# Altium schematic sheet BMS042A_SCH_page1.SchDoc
size 431 x 279 mm; Date: Not shown in title block; ApprovedBy: Not shown in title block; CheckedBy: Not shown in title block; Author: Not shown in title block; CompanyName: Not shown in title block; DrawnBy: Pengzhao Zhu; Engineer: Not shown in title block; Organization: Not shown in title block; Address1: Not shown in title block; Address2: Not shown in title block; Address3: Not shown in title block; Address4: Not shown in title block; DocumentNumber: 1; Revision: Use project parameter SCH_Rev; SheetNumber: 1; SheetTotal: 4; PageSetup: Record=PageOptions¦CenterHorizontal=True¦CenterVertical=True¦PrintScale=1.00¦XCorrection=1.00¦YCorrection=1.00¦PrintKind=0¦BorderSize=5000000¦LeftOffset=0¦BottomOffset=0¦Orientation=2¦PaperLength=1000¦PaperWidth=1000¦Scale=100¦PaperSource=15¦PrintQuality=600¦MediaType=1¦DitherType=10¦PaperKind=Letter¦PrintScaleMode=1
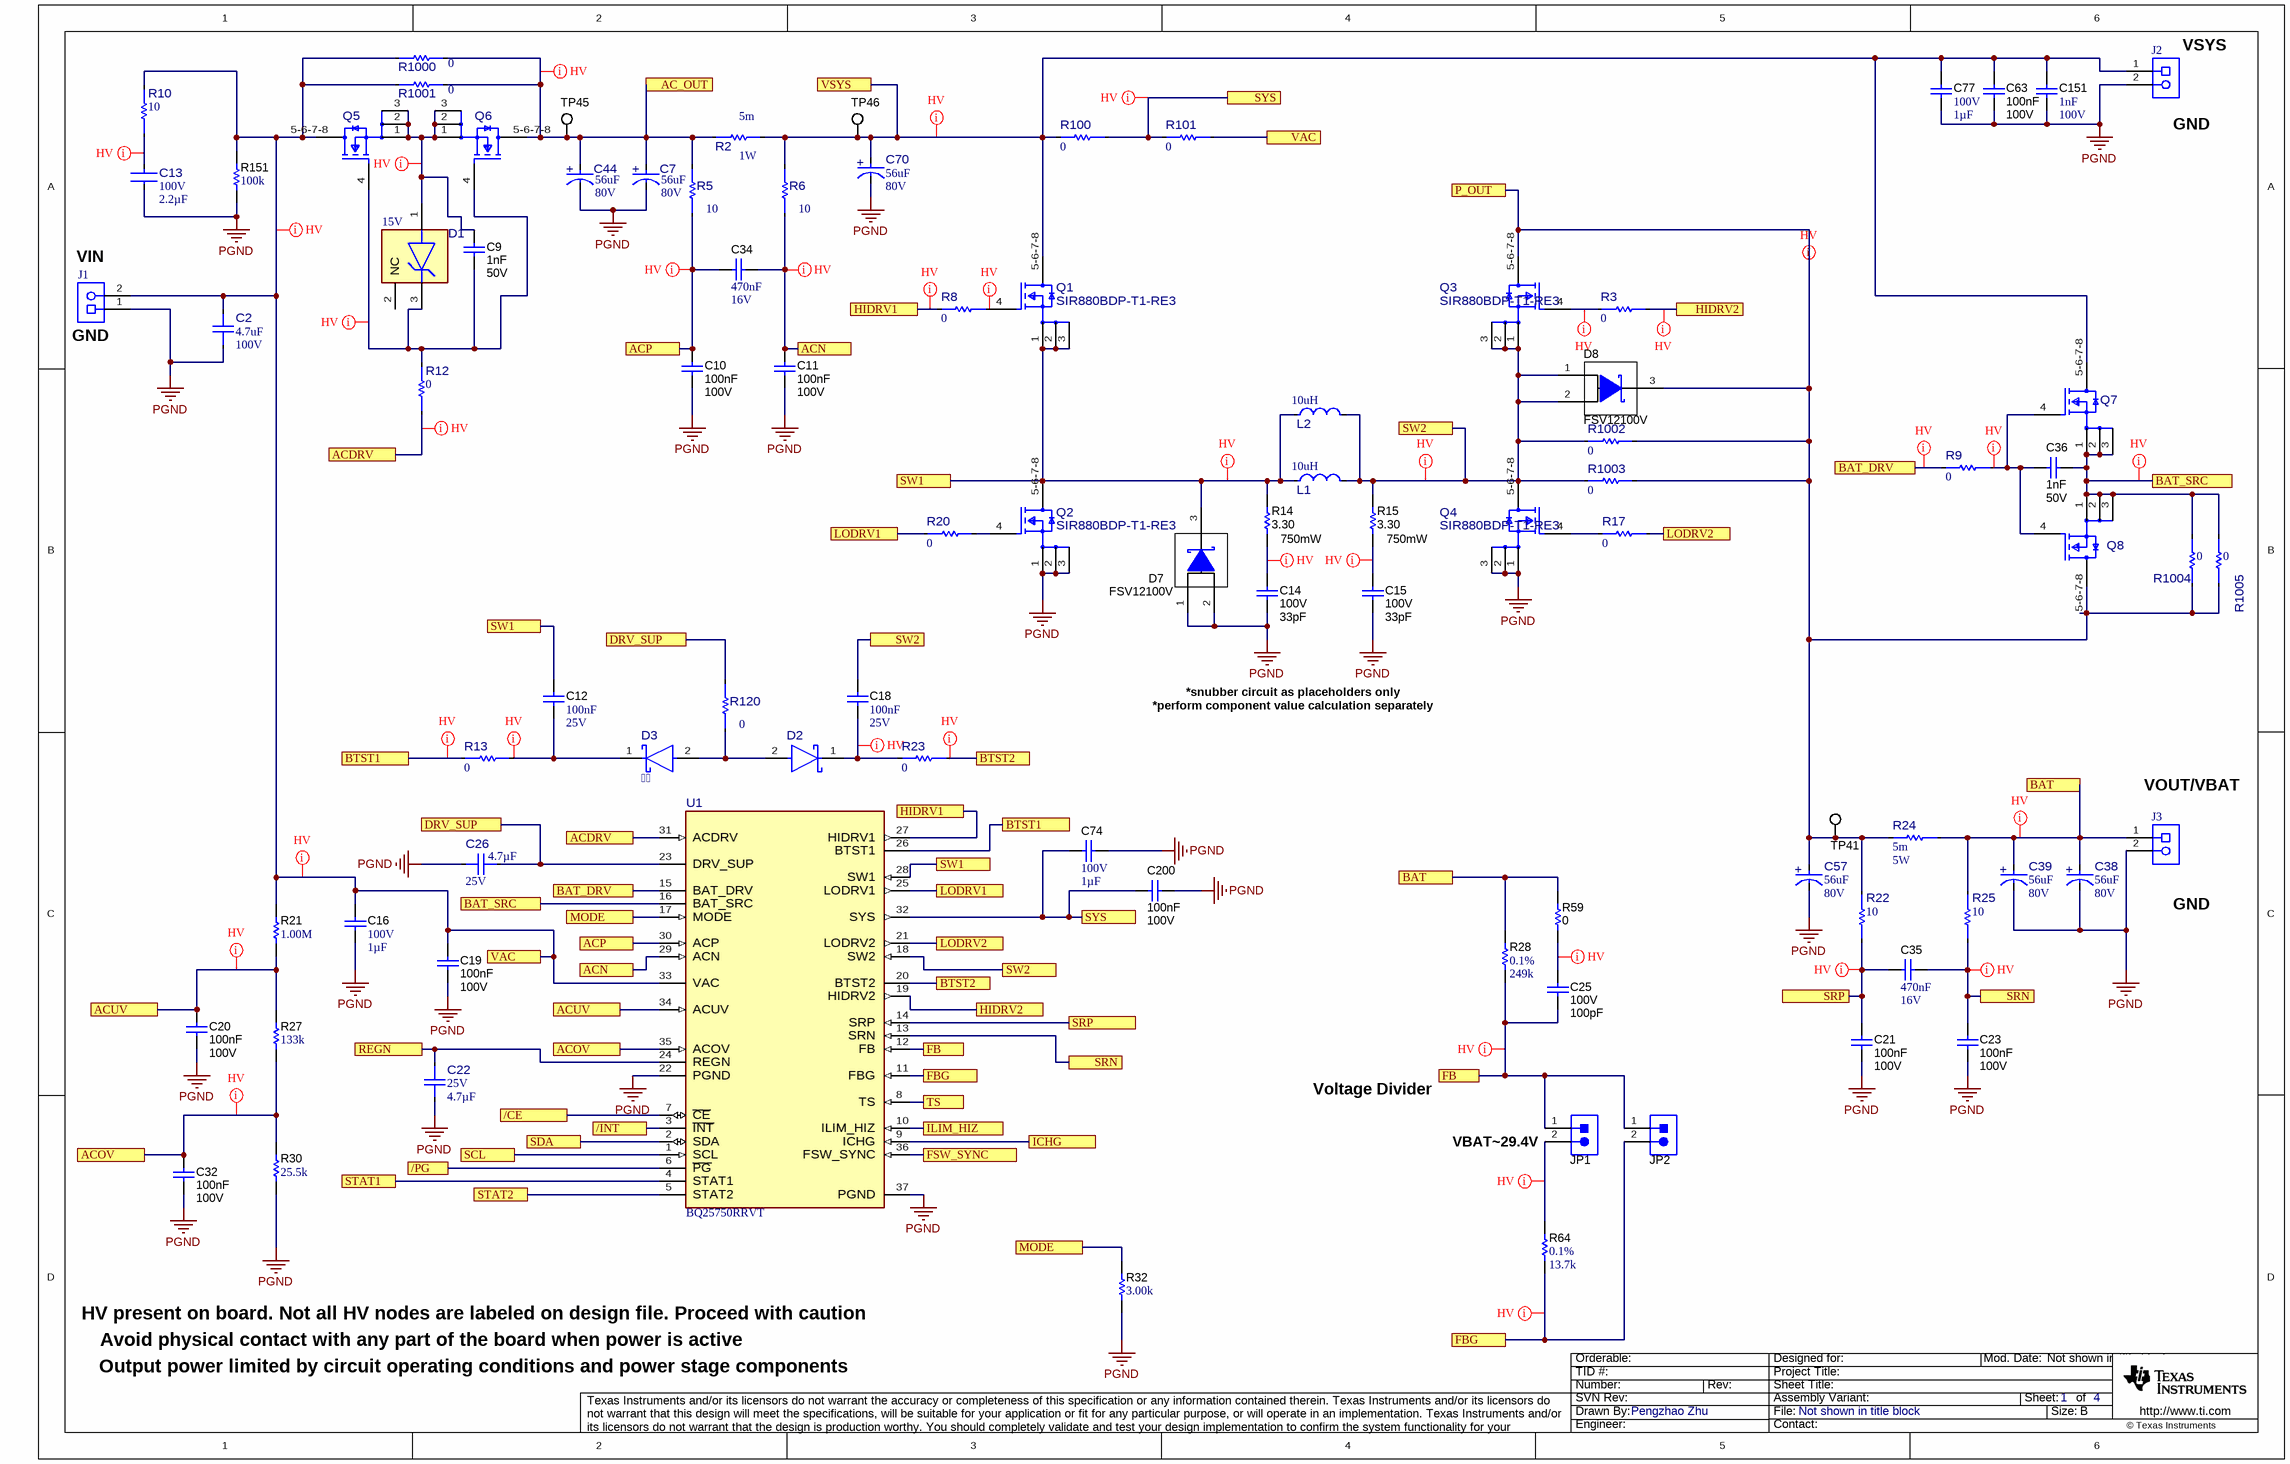
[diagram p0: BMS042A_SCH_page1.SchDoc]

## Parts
C2  ValueDisplayed: 4.7uF  VDC_V: 100V  [FP-GCJ32DC72A475KE01L_1210-MFG]  (hidden comment: GCJ32DC72A475KE01L)
C7  ValueDisplayed: 56uF  VDC_V: 80V  [FP-80SXV56M_SMT_CAP_10MM3_10MM3-MFG]  (hidden comment: 80SXV56M)
C9  Cap_F: 1nF  VDC_V: 50V  [0603_HV]  (hidden comment: C0603C102J5RACTU)
C10  Cap_F: 100nF  VDC_V: 100V  [0603_HV]  (hidden comment: HMK107B7104KAHT)
C11  Cap_F: 100nF  VDC_V: 100V  [0603_HV]  (hidden comment: HMK107B7104KAHT)
C12  Cap_F: 100nF  VDC_V: 25V  [0603_HV]  (hidden comment: 06033C104KAT2A)
C13  VDC_V: 100V  Cap_F: 2.2µF  [FP-CGA6N3X7R2A225K230AE_1210-MFG]  (hidden comment: CGA6N3X7R2A225K230AE)
C14  VDC_V: 100V  ValueDisplayed: 33pF  [0603_HV]  (hidden comment: 06031A330JAT2A)
C15  VDC_V: 100V  ValueDisplayed: 33pF  [0603_HV]  (hidden comment: 06031A330JAT2A)
C16  VDC_V: 100V  Cap_F: 1µF  [0805_150]  (hidden comment: 08051C105K4Z2A)
C18  Cap_F: 100nF  VDC_V: 25V  [0603_HV]  (hidden comment: 06033C104KAT2A)
C19  Cap_F: 100nF  VDC_V: 100V  [0603_HV]  (hidden comment: HMK107B7104KAHT)
C20  Cap_F: 100nF  VDC_V: 100V  [0603_HV]  (hidden comment: HMK107B7104KAHT)
C21  Cap_F: 100nF  VDC_V: 100V  [0603_HV]  (hidden comment: HMK107B7104KAHT)
C22  VDC_V: 25V  Cap_F: 4.7µF  [FP-CGA4J1X7R1E475K125AE_0805-MFG]  (hidden comment: CGA4J1X7R1E475K125AE)
C23  Cap_F: 100nF  VDC_V: 100V  [0603_HV]  (hidden comment: HMK107B7104KAHT)
C25  VDC_V: 100V  ValueDisplayed: 100pF  [0603_HV]  (hidden comment: GCM1885C2A101JA16D)
C26  VDC_V: 25V  Cap_F: 4.7µF  [FP-CGA4J1X7R1E475K125AE_0805-MFG]  (hidden comment: CGA4J1X7R1E475K125AE)
C32  Cap_F: 100nF  VDC_V: 100V  [0603_HV]  (hidden comment: HMK107B7104KAHT)
C34  Cap_F: 470nF  VDC_V: 16V  [0603]  (hidden comment: C0603C474K4RACTU)
C35  Cap_F: 470nF  VDC_V: 16V  [0603]  (hidden comment: C0603C474K4RACTU)
C36  Cap_F: 1nF  VDC_V: 50V  [0603_HV]  (hidden comment: C0603C102J5RACTU)
C38  ValueDisplayed: 56uF  VDC_V: 80V  [FP-80SXV56M_SMT_CAP_10MM3_10MM3-MFG]  (hidden comment: 80SXV56M)
C39  ValueDisplayed: 56uF  VDC_V: 80V  [FP-80SXV56M_SMT_CAP_10MM3_10MM3-MFG]  (hidden comment: 80SXV56M)
C44  ValueDisplayed: 56uF  VDC_V: 80V  [FP-80SXV56M_SMT_CAP_10MM3_10MM3-MFG]  (hidden comment: 80SXV56M)
C57  ValueDisplayed: 56uF  VDC_V: 80V  [FP-80SXV56M_SMT_CAP_10MM3_10MM3-MFG]  (hidden comment: 80SXV56M)
C63  Cap_F: 100nF  VDC_V: 100V  [0603L]  (hidden comment: HMK107B7104KAHT)
C70  ValueDisplayed: 56uF  VDC_V: 80V  [FP-80SXV56M_SMT_CAP_10MM3_10MM3-MFG]  (hidden comment: 80SXV56M)
C74  VDC_V: 100V  Cap_F: 1µF  [0805_150]  (hidden comment: 08051C105K4Z2A)
C77  VDC_V: 100V  Cap_F: 1µF  [0805_150]  (hidden comment: 08051C105K4Z2A)
C151  Cap_F: 1nF  VDC_V: 100V  [0603]  (hidden comment: CGA3E2X7R2A102K080AA)
C200  Cap_F: 100nF  VDC_V: 100V  [0603_HV]  (hidden comment: HMK107B7104KAHT)
D1  Vz_V: 15V  [FP-SZBZX84C15LT3G_SOT23-MFG]
D2  (no value)  [FP-V1FM10-M3-H_DO-219AB-MFG]
D3    [FP-V1FM10-M3-H_DO-219AB-MFG]
D7  FSV12100V  [TO-277A]
D8  FSV12100V  [TO-277A]
J1  (no value)  [FP-TB005-762-02BE_TERM_CONN-MFG]
J2  (no value)  [FP-TB005-762-02BE_TERM_CONN-MFG]
J3  (no value)  [FP-TB005-762-02BE_TERM_CONN-MFG]
JP1  PEC02SAAN  [CONN_PEC02SAAN]  (value not drawn)
JP2  PEC02SAAN  [CONN_PEC02SAAN]  (value not drawn)
L1  value 10uH  [FP-IHLP6767GZER100M01_SMT_INDUCTOR_17MM15_17MM15-MFG]  (hidden comment: IHLP6767GZER100M01)
L2  value 10uH  [FP-CMLB135T-100MS_SMT2_13MM45_12Mm6-MFG]  (hidden comment: CMLB135T-100MS)
Q1  SIR880BDP-T1-RE3  [FP-SIR880BDP-T1-RE3_SO-8-MFG]
Q2  SIR880BDP-T1-RE3  [FP-SIR880BDP-T1-RE3_SO-8-MFG]
Q3  SIR880BDP-T1-RE3  [FP-SIR880BDP-T1-RE3_SO-8-MFG]
Q4  SIR880BDP-T1-RE3  [FP-SIR880BDP-T1-RE3_SO-8-MFG]
Q5  (no value)  [FP-AONS66917_DFN8-MFG]
Q6  (no value)  [FP-AONS66917_DFN8-MFG]
Q7  (no value)  [FP-AONS66917_DFN8-MFG]
Q8  (no value)  [FP-AONS66917_DFN8-MFG]
R2  Res_ohm: 5m  Power_W: 1W  [FP-WSL25125L000FEA_2512-MFG]  (hidden comment: WSL25125L000FEA)
R3  value 0  [FP-CRCW06031R50FKEAHP_0603-MFG]  (hidden comment: CRCW06030000Z0EA)
R5  value 10  [FP-CRCW060310R0FKEB_0603-MFG]  (hidden comment: CRCW060310R0FKEB)
R6  value 10  [FP-CRCW060310R0FKEB_0603-MFG]  (hidden comment: CRCW060310R0FKEB)
R8  value 0  [FP-CRCW06031R50FKEAHP_0603-MFG]  (hidden comment: CRCW06030000Z0EA)
R9  value 0  [FP-CRCW06031R50FKEAHP_0603-MFG]  (hidden comment: CRCW06030000Z0EA)
R10  value 10  [FP-CRCW120610R0FKEAHP_1206-MFG]  (hidden comment: CRCW120610R0FKEAHP)
R12  value 0  [FP-CRCW06031R50FKEAHP_0603-MFG]  (hidden comment: CRCW06030000Z0EA)
R13  value 0  [FP-CRCW06031R50FKEAHP_0603-MFG]  (hidden comment: CRCW06030000Z0EA)
R14  Power_W: 750mW  ValueDisplayed: 3.30  [1210]  (hidden comment: CRCW12103R30FKEAHP)
R15  Power_W: 750mW  ValueDisplayed: 3.30  [1210]  (hidden comment: CRCW12103R30FKEAHP)
R17  value 0  [FP-CRCW06031R50FKEAHP_0603-MFG]  (hidden comment: CRCW06030000Z0EA)
R20  value 0  [FP-CRCW06031R50FKEAHP_0603-MFG]  (hidden comment: CRCW06030000Z0EA)
R21  ValueDisplayed: 1.00M  [0805_HV]  (hidden comment: CRCW08051M00FKEAC)
R22  value 10  [FP-CRCW060310R0FKEB_0603-MFG]  (hidden comment: CRCW060310R0FKEB)
R23  value 0  [FP-CRCW06031R50FKEAHP_0603-MFG]  (hidden comment: CRCW06030000Z0EA)
R24  value 5m  Power_W: 5W  [FP-FCSL110R005FER_WIDE_4320-MFG]  (hidden comment: FCSL110R005FER)
R25  value 10  [FP-CRCW060310R0FKEB_0603-MFG]  (hidden comment: CRCW060310R0FKEB)
R27  ValueDisplayed: 133k  [0805_HV]  (hidden comment: ERJ-6ENF1333V)
R28  Value1: 0.1%  ValueDisplayed: 249k  [0805_HV]  (hidden comment: ERJ-PB6B2493V)
R30  ValueDisplayed: 25.5k  [0805_HV]  (hidden comment: ERJ-6ENF2552V)
R32  ValueDisplayed: 3.00k  [0805_HV]  (hidden comment: ERJ-6ENF3001V)
R59  ValueDisplayed: 0  [0805_HV]  (hidden comment: RC0805JR-070RL)
R64  Tolerance_%: 0.1%  ValueDisplayed: 13.7k  [0805_HV]  (hidden comment: RG2012P-1372-B-T5)
R100  value 0  [FP-CRCW06031R50FKEAHP_0603-MFG]  (hidden comment: CRCW06030000Z0EA)
R101  value 0  [FP-CRCW06031R50FKEAHP_0603-MFG]  (hidden comment: CRCW06030000Z0EA)
R120  value 0  [FP-CRCW080510R0JNEAHP_0805-MFG]  (hidden comment: CRCW08050000Z0EA)
R151  ValueDisplayed: 100k  [1210]  (hidden comment: RC1210JR-07100KL)
R1000  value 0  [FP-JR0805X35E_0805-MFG]  (hidden comment: JR0805X35E)
R1001  value 0  [FP-JR0805X35E_0805-MFG]  (hidden comment: JR0805X35E)
R1002  value 0  [FP-JR0805X35E_0805-MFG]  (hidden comment: JR0805X35E)
R1003  value 0  [FP-JR0805X35E_0805-MFG]  (hidden comment: JR0805X35E)
R1004  value 0  [FP-JR0805X35E_0805-MFG]  (hidden comment: JR0805X35E)
R1005  value 0  [FP-JR0805X35E_0805-MFG]  (hidden comment: JR0805X35E)
TP41  5002  [Keystone5002]  (value not drawn)
TP45  5002  [Keystone5002]  (value not drawn)
TP46  5002  [Keystone5002]  (value not drawn)
U1  BQ25750RRVT  [RRV0036A-MFG]

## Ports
/CE, /INT, /PG, AC_OUT, ACDRV, ACN, ACOV, ACP, ACUV, BAT, BAT_DRV, BAT_SRC, BTST1, BTST2, DRV_SUP, FB, FBG, FSW_SYNC, HIDRV1, HIDRV2, ICHG, ILIM_HIZ, LODRV1, LODRV2, MODE, P_OUT, REGN, SCL, SDA, SRN, SRP, STAT1, STAT2, SW1, SW2, SYS, TS, VAC, VSYS

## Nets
PGND: C2.1 C7.1(CATHODE) C10.2 C11.2 C13.2 C14.2 C15.2 C16.2 C19.2 C20.2 C21.2 C22.2 C23.2 C26.2 C32.2 C38.1(CATHODE) C39.1(CATHODE) C44.1(CATHODE) C57.1(CATHODE) C63.2 C70.1(CATHODE) C74.2 C77.2 C151.2 C200.2 D7.1(A) D7.2(A) J1.1 J2.2 J3.2 Q2.1(S) Q2.2(S) Q2.3(S) Q4.1(S) Q4.2(S) Q4.3(S) R30.1 R32.1 R151.1 U1.22(PGND) U1.37(PGND)
/CE: U1.7(~{CE}) ; port /CE
/INT: U1.3(~{INT}) ; port /INT
/PG: U1.6(~{PG}) ; port /PG
AC_OUT: C7.2(ANODE) C44.2(ANODE) Q6.5-6-7-8(D) R2.1 R5.2 R1000.2 R1001.2 TP45.1 ; port AC_OUT
ACDRV: R12.1 U1.31(ACDRV) ; port ACDRV
ACN: C11.1 C34.2 R6.1 U1.29(ACN) ; port ACN
ACOV: C32.1 R27.1 R30.2 U1.35(ACOV) ; port ACOV
ACP: C10.1 C34.1 R5.1 U1.30(ACP) ; port ACP
ACUV: C20.1 R21.1 R27.2 U1.34(ACUV) ; port ACUV
BAT: C38.2(ANODE) C39.2(ANODE) J3.1 R24.1 R25.1 R28.2 R59.2 ; port BAT
BAT_DRV: R9.2 U1.15(BAT_DRV) ; port BAT_DRV
BAT_SRC: C36.2 Q7.1(S) Q7.2(S) Q7.3(S) Q8.1(S) Q8.2(S) Q8.3(S) R1004.2 R1005.2 U1.16(BAT_SRC) ; port BAT_SRC
BTST1: R13.1 U1.26(BTST1) ; port BTST1
BTST2: R23.1 U1.20(BTST2) ; port BTST2
DRV_SUP: C26.1 R120.2 U1.23(DRV_SUP) ; port DRV_SUP
FB: C25.2 JP1.1 JP2.1 R28.1 U1.12(FB) ; port FB
FBG: JP2.2 R64.1 U1.11(FBG) ; port FBG
FSW_SYNC: U1.36(FSW_SYNC) ; port FSW_SYNC
HIDRV1: R8.2 U1.27(HIDRV1) ; port HIDRV1
HIDRV2: R3.2 U1.19(HIDRV2) ; port HIDRV2
ICHG: U1.9(ICHG) ; port ICHG
ILIM_HIZ: U1.10(ILIM_HIZ) ; port ILIM_HIZ
LODRV1: R20.1 U1.25(LODRV1) ; port LODRV1
LODRV2: R17.1 U1.21(LODRV2) ; port LODRV2
MODE: R32.2 U1.17(MODE) ; port MODE
P_OUT: C57.2(ANODE) D8.3(K) Q3.5-6-7-8(D) Q8.5-6-7-8(D) R22.1 R24.2 R1002.2 R1003.2 R1004.1 R1005.1 TP41.1 ; port P_OUT
REGN: C22.1 U1.24(REGN) ; port REGN
SCL: U1.1(SCL) ; port SCL
SDA: U1.2(SDA) ; port SDA
SRN: C23.1 C35.2 R25.2 U1.13(SRN) ; port SRN
SRP: C21.1 C35.1 R22.2 U1.14(SRP) ; port SRP
STAT1: U1.4(STAT1) ; port STAT1
STAT2: U1.5(STAT2) ; port STAT2
SW1: C12.1 D7.3(K) L1.1 L2.1 Q1.1(S) Q1.2(S) Q1.3(S) Q2.5-6-7-8(D) R14.2 U1.28(SW1) ; port SW1
SW2: C18.2 D8.1(A) D8.2(A) L1.2 L2.2 Q3.1(S) Q3.2(S) Q3.3(S) Q4.5-6-7-8(D) R15.2 R1002.1 R1003.1 U1.18(SW2) ; port SW2
SYS: C74.1 C200.1 R100.1 R101.2 U1.32(SYS) ; port SYS
TS: U1.8(TS) ; port TS
VAC: C2.2 C16.1 C19.1 J1.2 Q5.5-6-7-8(D) R10.2 R21.2 R101.1 R151.2 R1000.1 R1001.1 U1.33(VAC) ; port VAC
VSYS: C63.1 C70.2(ANODE) C77.1 C151.1 J2.1 Q1.5-6-7-8(D) Q7.5-6-7-8(D) R2.2 R6.2 R100.2 TP46.1 ; port VSYS
NetC9_1: C9.1 D1.1(Anode) Q5.1(S) Q5.2(S) Q5.3(S) Q6.1(S) Q6.2(S) Q6.3(S)
NetC9_2: C9.2 D1.3(Cathode) Q5.4(G) Q6.4(G) R12.2
NetC12_2: C12.2 D3.1(CATHODE) R13.2
NetC13_1: C13.1 R10.1
NetC14_1: C14.1 R14.1
NetC15_1: C15.1 R15.1
NetC18_1: C18.1 D2.1(CATHODE) R23.2
NetC25_1: C25.1 R59.1
NetC36_1: C36.1 Q7.4(G) Q8.4(G) R9.1
NetD2_2: D2.2(ANODE) D3.2(ANODE) R120.1
NetJP1_2: JP1.2 R64.2
NetQ1_4: Q1.4(G) R8.1
NetQ2_4: Q2.4(G) R20.2
NetQ3_4: Q3.4(G) R3.1
NetQ4_4: Q4.4(G) R17.2

Not connected (* = marked no-connect by the designer): D1 2(NC)

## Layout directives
net class HV: AC_OUT, ACDRV, ACN, ACOV, ACP, ACUV, BAT, BAT_DRV, BAT_SRC, BTST1, BTST2, FB, FBG, HIDRV1, HIDRV2, NetC9_1, NetC9_2, NetC12_2, NetC13_1, NetC14_1, NetC15_1, NetC18_1, NetC25_1, NetC36_1, NetJP1_2, NetQ1_4, NetQ3_4, P_OUT, SRN, SRP, SW1, SW2, SYS, VAC, VSYS

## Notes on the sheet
- (near J2) VSYS
- (near J2) GND
- (near J1) VIN
- (near J1) GND
- *snubber circuit as placeholders only
- *perform component value calculation separately
- (near J3) VOUT/VBAT
- (near J3) GND
- Voltage Divider
- (near JP1) VBAT|9.4V
- Avoid physical contact with any part of the board when power is active
- HV present on board. Not all HV nodes are labeled on design file. Proceed with caution
- Output power limited by circuit operating conditions and power stage components

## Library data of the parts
C2 = CMP-0093675-1: 4.7uF ±10% 100V Ceramic Capacitor X7S 1210 (3225 Metric); Manufacturer: Murata; Value: 4.7µF; AEC Qualified: Yes; TempCo: 22%; SizeZ_mm: 2.3mm; AEC Grade: Grade 1
C7 C38 C39 C44 C57 C70 = CMP-0093756-1: 56 µF 80 V Aluminum - Polymer Capacitors Radial, Can - SMD 28mOhm 1000 Hrs @ 125°C; Manufacturer: Panasonic; Life: 1000Hours; Esr: 28m; IRMS_A: 3.1A; Leakage Current: 224uA; Tolerance_%: 20%; Cap_F: 56µF; AEC Qualified: No; Dissipation Factor: 12%; SizeZ_mm: 12.7mm; Value: 56µF
C9 C36 = CMP-0006845-4: CAP, CERM, 1000 pF, 50 V, +/- 5%, X7R, 0603; Manufacturer: Kemet; TaMin_C: -55°C; Polarized: N; SizeAreaWB_mm2: 4.68; Value1: Unknown; U/M: EA; Value: 1000pF; TaMax_C: 125°C; SizeZ_mm: 1; SizeX_mm: 1.6; SizeY_mm: 0.8; Cap_Case: 0603; SizeArea_mm2: 1.28; AEC Category: Q200
C10 C11 C19-C21 C23 C32 C63 C200 = CMP-0081011-1: CAP, CERM, 0.1 µF, 100 V,+/- 10%, X7R, AEC-Q200 Grade 1, 0603; Manufacturer: Taiyo Yuden; SizeAreaWB_mm2: 4.68; SizeArea_mm2: 1.28; AEC Qualified: Y; AEC Category: Q200; Value: 0.1uF; TaMax_C: 125°C; SizeZ_mm: 1; Polarized: N; TaMin_C: -55°C; SizeY_mm: 0.8; U/M: EA; SizeX_mm: 1.6; Cap_Case: 0603; ValueDisplayed: 0.1µF
C12 C18 = CMP-0006753-4: CAP, CERM, 0.1 uF, 25 V, +/- 10%, X7R, 0603; Manufacturer: AVX; TaMin_C: -55°C; ESR_ohm: 50m; Polarized: N; SizeAreaWB_mm2: 4.68; Value1: 0.05 ohm; U/M: EA; Value: 0.1uF; TaMax_C: 125°C; SizeZ_mm: 1; SizeX_mm: 1.6; SizeY_mm: 0.8; Cap_Case: 0603; SizeArea_mm2: 1.28; AEC Category: Q200
C13 = CMP-0087124-1: Cap Ceramic 2.2uF 100V X7R 10% SMD 1210 FlexiTerm 125C Plastic T/R; Manufacturer: TDK Corporation; TempCo: 15%; AEC Qualified: Yes; SizeZ_mm: 2.6mm; AEC Grade: Grade 1
C14 C15 = CMP-0006722-4: CAP, CERM, 33 pF, 100 V, +/- 5%, C0G/NP0, 0603; Manufacturer: AVX; TaMin_C: -55°C; ESR_ohm: 0.209; Polarized: N; SizeAreaWB_mm2: 4.68; Value1: 0.209 ohm; U/M: EA; Value: 33pF; TaMax_C: 125°C; SizeZ_mm: 1; SizeX_mm: 1.6; SizeY_mm: 0.8; Cap_Case: 0603; SizeArea_mm2: 1.28; AEC Category: Q200
C16 C74 C77 = CMP-0861070-1: CAP, CERM, 1 µF, 100 V,+/- 10%, X7R, AEC-Q200 Grade 1, 0805; Manufacturer: AVX; SizeZ_mm: 1.5; Polarized: N; TaMax_C: 125°C; TaMin_C: -55°C; Value: 1uF; AEC Qualified: Y; U/M: EA; AEC Grade: 1; Cap_Case: 0805; SizeX_mm: 2; SizeArea_mm2: 2.5; SizeAreaWB_mm2: 6.75; AEC Category: Q200; SizeY_mm: 1.25
C22 C26 = CMP-0093626-1: Cap Ceramic 4.7uF 25V X7R 10% Pad SMD 0805 +125°C Automotive T/R; Manufacturer: TDK Corporation; SizeZ_mm: 1.45mm; TempCo: 15%; AEC Qualified: Yes; Value: 4.7µF; Tolerance_%: 0.1%; AEC Grade: Grade 1
C25 = CMP-0007130-4: CAP, CERM, 100 pF, 100 V, +/- 5%, C0G/NP0, AEC-Q200 Grade 1, 0603; Manufacturer: MuRata; TaMin_C: -55°C; Polarized: N; SizeAreaWB_mm2: 4.68; Value1: Unknown; U/M: EA; TaMax_C: 125°C; SizeZ_mm: 1; SizeX_mm: 1.6; SizeY_mm: 0.8; Cap_Case: 0603; SizeArea_mm2: 1.28; AEC Qualified: Y; AEC Category: Q200; Value: 100pF
C34 C35 = CMP-0006944-4: CAP, CERM, 0.47 uF, 16 V, +/- 10%, X7R, 0603; Manufacturer: Kemet; TaMin_C: -55°C; Polarized: N; SizeAreaWB_mm2: 4.68; Value1: Unknown; U/M: EA; Value: 0.47uF; TaMax_C: 125°C; SizeZ_mm: 1; SizeX_mm: 1.6; SizeY_mm: 0.8; SizeArea_mm2: 1.28; AEC Category: Q200
C151 = CMP-0007081-4: Multilayer Ceramic Capacitors MLCC - SMD/SMT CGA 0603 100V 1000pF X7R 10% AEC-Q200; Manufacturer: TDK; TaMin_C: -55°C; ESR_ohm: 1.9714; Polarized: N; SizeAreaWB_mm2: 4.68; Value1: 1.97137 ohm; U/M: EA; TaMax_C: 125°C; SizeZ_mm: 1; SizeX_mm: 1.6; SizeY_mm: 0.8; SizeArea_mm2: 1.28; AEC Qualified: Y; IRMS_A: 305.705mA; AEC Category: Q200
D1 = CMP-0093134-1: Zener Diode Single 15V 5% 30Ohm 300mW Automotive 3-Pin SOT-23 T/R; Part Number: SZBZX84C15LT3G; Manufacturer: On Semiconductor; TJmax_C: +150°C; SizeZ_mm: 1.11mm; Power_W: 250mW; Ciiva Ids: 807354; VRWM: 15.6V; Vr_V: 10.5V; AEC Grade: Grade 0; Standoff Height: 0.01mm; Max Reverse Leakage Current: 0.05uA; Zener Impedance: 30Ω; Import Ts: 1521856680; AEC Qualified: Yes
D2 D3 = CMP-0093639-2: Diode Schottky 1A Surface Mount DO-219AB (SMF); Part Number: V1FM10-M3/H; Manufacturer: Vishay; Max Surge Forward Current: 30A; TJmax_C: 175°C; AEC Qualified: No; Cap_F: 95pF; AEC Category: Q101; Standoff Height: 0mm; SizeZ_mm: 1.08mm; Vr_V: 100V; Peak Reverse Current: 0.2uA
D7 D8 = CMP-0028821-2: Diode, Schottky, 100 V, 12 A, AEC-Q101, TO-277A; Manufacturer: Fairchild Semiconductor; TJmax_C: 150°C; Green_Lifecycle: Not Set; Vr_V: 100V; Value: 100V; SizeY_mm: 4.75; Vf_V: 670mV; Green_REACh: Incomplete; SizeAreaWB_mm2: 57.375; SizeX_mm: 6.5; SizeArea_mm2: 30.875; Value2: 0.67V; Io_A: 12A; AEC Qualified: Y; SizeZ_mm: 1.2; AEC Category: Q101
J1-J3 = CMP-0093294-2: PartNumber: TB005-762-02BE; Manufacturer: CUI Devices; Min Wire Gauge: 26; ContactFinish: Tin; Conn Gender: Female; Conn Orientation: Horizontal; DUT-Pitch_mm: 7.62mm; AEC Qualified: No; Row_Count: 1; SizeZ_mm: 22.1mm; Max Wire Gauge: 10; Voltage_V: 300V; Current_A: 30A; Is Female: yes
JP1 JP2 = CMP-0002337-1: Header, 100mil, 2x1, Tin, TH; Manufacturer: Sullins Connector Solutions; Cert_UL: Y; CNHeader: TRUE; CT: FALSE; Current_A: 3A; Gender: Male; Green_Lifecycle: Not Set; Green_REACh: Incomplete; Pitch_mm: 2.54; Row_Count: 1; Shrouded: N; Voltage_V: 1.8kV
L1 = CMP-0093259-1: Commercial Inductors, High Saturation Series 10uH 16.5A 12mΩ 20%; Manufacturer: Vishay; Material: SMC; SizeZ_mm: 7mm; Shrouded: true; Isat: 25A; DCR_ohm: 12m; Test Frequency: 100kHz; AEC Qualified: No; Ind_H: 10µH
L2 = CMP-0096007-1: Power Choke Coil 10uH 20% 9A 22mOhm; Manufacturer: Cyntec; Material: Metal Dust; SizeZ_mm: 5mm; Standoff Height: 0mm; Ind_H: 10µH; AEC Qualified: No; Isat: 10.5A; Test Frequency: 100kHz; DCR_ohm: 22m
Q1-Q4 = CMP-0096839-1: N-Channel 80 V 18.6A (Ta), 70.6A (Tc) 5W (Ta), 71.4W (Tc) Surface Mount PowerPAK® SO-8; Manufacturer: Vishay; QgTyp_nC: 43.5nC @ 10V; Turn On Delay Time: 12ns; Rthja Max: 20°C/W; Turn Off Delay Time: 40ns; Reverse Recovery Charge: 52nC; Typ Forward Diode Voltage: 0.74V; VdsMax_V: 1.1V; SizeZ_mm: 1.12mm; Number Of Channels: 1; Pulse Drain Current: 200A; Threshold Vgs Min: 1V; TJmax_C: +150°C; AEC Qualified: No; Transconductance: 49S; ChMode: False; Reverse Recovery Time: 38ns; Threshold Vgs Max: 2.4V; Input Capacitace At Vds: 2930pF @ 40V; Vgs_V: 20V; Drain To Source Breakdown Voltage: 80V; Rdson45_ohm: 5.3m
Q5-Q8 = CMP-0093242-3: 100V N-Channel MOSFET, DFN5x6-8L, RoHS; Part Number: AONS66917; Manufacturer: Alpha & Omega Semiconductor; Threshold Vgs Max: 2.8V; Vgs_V: 20V; QgTyp_nC: 80nC @ 10V; AEC Qualified: No; Power_W: 6.2W; Number Of N Channels: 1; TJmax_C: +150°C; Reverse Recovery Time: 43ns; Threshold Vgs Min: 1.7V; Turn Off Delay Time: 46ns; Standoff Height: 0mm; Input Capacitace At Vds: 5940pF @ 50V; Pulse Drain Current: 320A; Reverse Recovery Charge: 208nC; Rdson45_ohm: 2.9m; IdsMax_A: 100A; Transconductance: 100S; ChMode: False; Turn On Delay Time: 16.5ns; VdsMax_V: 1V; SizeZ_mm: 1.05mm; Typ Forward Diode Voltage: 0.68V; Rthja Max: 40°C/W
R2 = CMP-0096841-1: Res Metal Strip 2512 0.005 Ohm 1% 1W 110ppm/C Molded SMD SMD Embossed Plastic T/R; Manufacturer: Vishay; TempCo: 110ppm/°C; AEC Grade: Grade 0; AEC Qualified: Yes; Category 5A00970A6D5C81C7: Uncategorized; Value: 5m; Category 5C6A91606D4187Ad: Resistors; Category Cd01000Bfc2916C6: Single Components; Category 7542B8484461Ae85: Passive Components; SizeZ_mm: 0.889mm
R3 R8 R9 R12 R13 R17 R20 R23 R100 R101 = CMP-0093629-1: Thick Film Resistors - SMD 1/10watt ZEROohm Jumper; Manufacturer: Vishay; AEC Grade: Grade 0; TempCo: 100ppm/°C; Power: 250mW; Res_ohm: 1.5; Power_W: 330mW; AEC Qualified: Yes; VDC_V: 75V; SizeZ_mm: 0.55mm; Tolerance_%: 1%
R5 R6 R22 R25 = CMP-0093685-1: RES Thick Film, 10Ω, 1%, 0.1W, 100ppm/°C, 0603; Manufacturer: Vishay; Approved Alternate Part Number: 541-1.00HHCT-ND; Power_W: 100mW; Voltage: 75V; SizeZ_mm: 0.5mm; AEC Grade: Grade 0; AEC Qualified: Yes
R10 = CMP-0093410-1: RES Thick Film, 10Ω, 1%, 0.75W, 100ppm/°C, 1206; Manufacturer: Vishay Dale; AEC Qualified: Yes; VDC_V: 200V; SizeZ_mm: 0.65mm; AEC Grade: Grade 0; Power_W: 750mW
R14 R15 = CMP-0015022-3: RES, 3.30, 1%, 0.75 W, AEC-Q200 Grade 0, 1210; Manufacturer: Vishay-Dale; TempCo: 100 ppm/C; SizeAreaWB_mm2: 14.7; Value_Code: 3R30; Value: 3.30; Res_ohm: 3.3; SizeX_mm: 3.2; SizeY_mm: 2.5; SizeZ_mm: 1.35; Value2: 0.75W; SizeArea_mm2: 8; AEC Qualified: Y; AEC Grade: 0; AEC Category: Q200
R21 = CMP-0021522-3: Thick Film Resistors - SMD 1/8Watt 1Mohms 1% Commercial Use; Manufacturer: Vishay / Dale; Power_W: 125mW; TempCo: 100 ppm/C; Value_Code: 1M00; Value: 1.00Meg; EIA_Code: E96; Res_ohm: 1M; SizeX_mm: 2; SizeY_mm: 1.25; SizeZ_mm: 1.45; Value2: 0.125W; SizeArea_mm2: 2.5; AEC Qualified: Y; AEC Category: Q200; AEC Grade: 0; SizeAreaWB_mm2: 6.75
R24 = CMP-0093177-1: 5 mOhms ±1% 5W Chip Resistor Wide 4320 (11050 Metric), 2043 Current Sense, Moisture Resistant Metal Foil; Manufacturer: Ohmite; AEC Qualified: No; TempCo: 50ppm/°C; SizeZ_mm: 0.7mm
R27 = CMP-0021561-3: RES, 133 k, 1%, 0.125 W, AEC-Q200 Grade 0, 0805; Manufacturer: Panasonic; Power_W: 125mW; TempCo: 100 ppm/C; Value: 133k; EIA_Code: E96; SizeX_mm: 2; SizeY_mm: 1.25; SizeZ_mm: 1.45; Value2: 0.125W; SizeArea_mm2: 2.5; AEC Qualified: Y; AEC Category: Q200; AEC Grade: 0; SizeAreaWB_mm2: 6.75
R28 = CMP-0018933-2: Thick Film Resistors - SMD 0805 Anti-Surge Res. 0.1%, 249Kohm; Manufacturer: Panasonic; Power_W: 125mW; TempCo: 25 ppm/C; U/M: EA; Value: 249k; EIA_Code: E192; SizeX_mm: 2; SizeY_mm: 1.25; SizeZ_mm: 1.45; Value2: 0.125W; SizeArea_mm2: 2.5; VDC_V: 100V; AEC Category: Q200
R30 = CMP-0021646-3: RES, 25.5 k, 1%, 0.125 W, AEC-Q200 Grade 0, 0805; Manufacturer: Panasonic; Power_W: 125mW; TempCo: 100 ppm/C; Value_Code: 25k5; Value: 25.5k; EIA_Code: E96; SizeX_mm: 2; SizeY_mm: 1.25; SizeZ_mm: 1.45; Value2: 0.125W; SizeArea_mm2: 2.5; AEC Qualified: Y; AEC Category: Q200; AEC Grade: 0; SizeAreaWB_mm2: 6.75
R32 = CMP-0021666-2: RES, 3.00 k, 1%, 0.125 W, AEC-Q200 Grade 0, 0805; Manufacturer: Panasonic; Power_W: 125mW; TempCo: 100 ppm/C; Value_Code: 3k00; U/M: EA; Value: 3.00k; Res_ohm: 3k; SizeX_mm: 2; SizeY_mm: 1.25; SizeZ_mm: 1.45; Value2: 0.125W; SizeArea_mm2: 2.5; AEC Qualified: Y; VDC_V: 150V; AEC Grade: 0; AEC Category: Q200
R59 = CMP-0020803-2: RES, 0, 5%, 0.125 W, 0805; Manufacturer: Yageo America; Power_W: 125mW; TempCo: 200 ppm/C; Value_Code: 0000; U/M: EA; Value: 0; EIA_Code: E24; SizeX_mm: 2; SizeY_mm: 1.25; SizeZ_mm: 1.45; Value2: 0.125W; SizeArea_mm2: 2.5; VDC_V: 150V; AEC Category: Q200
R64 = CMP-0018881-2: RES, 13.7 k, 0.1%, 0.125 W, 0805; Manufacturer: Susumu Co Ltd; Power_W: 125mW; TempCo: 25 ppm/C; Value_Code: 13k7; U/M: EA; Value: 13.7k; EIA_Code: E192; SizeX_mm: 2; SizeY_mm: 1.25; SizeZ_mm: 1.45; Value2: 0.125W; SizeArea_mm2: 2.5; VDC_V: 100V; AEC Category: Q200
R120 = CMP-0092857-1: Thick Film Resistors - SMD 1/8watt ZEROohm Jumper; Manufacturer: Vishay; Power_W: 500mW; SizeZ_mm: 0.6mm; AEC Qualified: Yes; TempCo: 200ppm/°C; VDC_V: 150V; Tolerance_%: 5%; AEC Grade: Grade 0
R151 = CMP-0083440-1: RES, 100 k, 5%, 0.5 W, 1210; Manufacturer: Yageo; Power_W: 500mW; TempCo: 100 ppm/C; SizeAreaWB_mm2: 14.7; Value: 100k; EIA_Code: E24; SizeX_mm: 3.2; SizeY_mm: 2.5; SizeZ_mm: 1.35; Value2: 0.5W; SizeArea_mm2: 8; AEC Qualified: N; VDC_V: 200V; AEC Category: Q200
R1000-R1005 = CMP-0096818-1: 0 Ohms Jumper 0.245W Chip Resistor 0805 (2012 Metric) - Metal Element; Manufacturer: Ohmite; AEC Qualified: No; Power_W: 245mW; SizeZ_mm: 0.55mm
TP41 TP45 TP46 = CMP-0055139-1: Test Point, Miniature, White, TH; Manufacturer: Keystone; CNHeader: FALSE; ContactFinish: Silver; CT: TRUE; Green_Lifecycle: Active; Green_REACh: Passed
U1 = CMP-0091286-5: Standalone/I2C Controlled, 70V, 20A Buck-Boost Multi-Chemistry Battery Charge Controller; Manufacturer: Texas Instruments; Number Of Cells: 16; AEC Qualified: No; Number Of Outputs: 1; SizeZ_mm: 1mm; TJmax_C: +125°C; AEC Category: Q200; CompType: IC; Min Supply Voltage: 4.2V; TaMin_C: -40°C; Standoff Height: 0mm; Output Voltage: 0-60V; TaMax_C: +105°C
